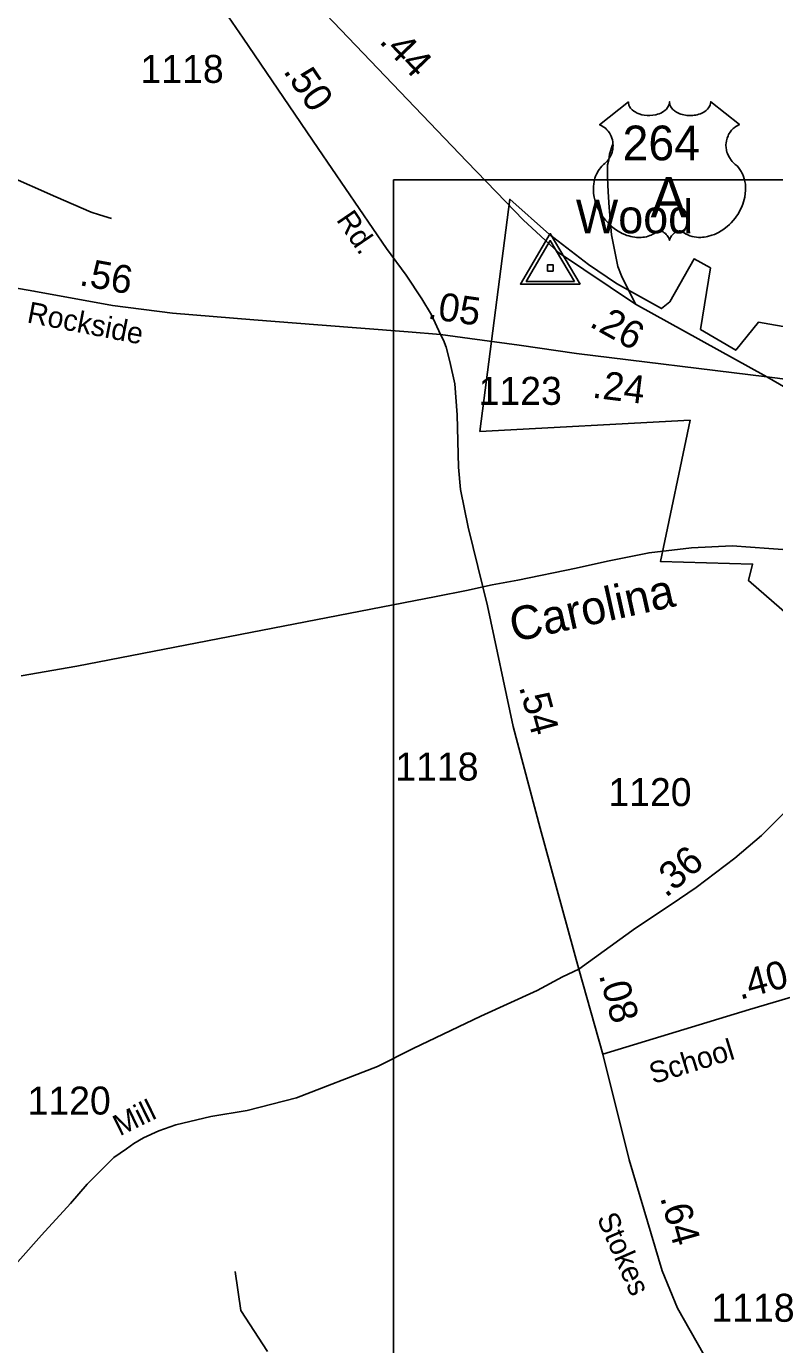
# Model space of a CAD drawing. Extents: x 2220236 to 2384410, y 720751 to 894131.
# Drawn here: x 2229809 to 2233152, y 740224 to 746114 of the extents above; entities that cross this region are included whole.
import ezdxf

# ---------------------------------------------------------------- set-up
doc = ezdxf.new("R2010")
doc.units = 0
doc.layers.add('Default', color=7, linetype='Continuous')

msp = doc.modelspace()

# ---------------------------------------------------------------- linework, layer by layer
at = {"layer": 'Default'}
msp.add_line((2232384.7, 741521.8), (2232276.8, 741902.5), dxfattribs=at)
for points in [[(2231659.5, 744737.4), (2231619.3, 744825.2), (2231575.4, 744896.6), (2231505.9, 745002.7), (2231418.1, 745121.7), (2231112.4, 745569.3), (2230777.7, 746061.6), (2230580.2, 746348.9), (2230512.5, 746456.9), (2230463.1, 746550.2), (2230430.2, 746627.1), (2230406.4, 746714.9), (2230384.5, 746824.7), (2230361.1, 746991.9)], [(2230361.1, 746991.9), (2230447.5, 746900.6), (2230620, 746722.5), (2230949.2, 746376.9), (2231776.5, 745511.2), (2231950.2, 745330.8), (2232027.5, 745250.6), (2232186.5, 745104.3), (2232530.4, 744873.7), (2233116.5, 744547.9)], [(2232427, 745585.6), (2232414.2, 745543.5), (2232410.6, 745517.9), (2232405.1, 745495.9), (2232405.1, 745468.5), (2232405.1, 745439.2), (2232406.9, 745406.2), (2232408.7, 745375.1), (2232412.4, 745305.6), (2232423.4, 745183), (2232450.8, 745042), (2232467.3, 744999.9), (2232530.4, 744873.7)], [(2229152, 745060.9), (2229225.1, 745149.1), (2229349.5, 745299.2), (2229462.9, 745452.9), (2229501.3, 745496.9), (2229521.4, 745511.5), (2229532.4, 745515.2), (2229550.1, 745516.1), (2229570.8, 745513.3), (2229616.5, 745498.7), (2229718.9, 745451.1), (2229940.3, 745352.3), (2230097.5, 745284.6), (2230136, 745271.8), (2230189, 745255.3)], [(2231448.3, 745428), (2239755.4, 745428), (2239755.4, 740165.1), (2231448.3, 740165.1), (2231448.3, 745428)], [(2233447.8, 743279.8), (2233035, 743638), (2233053.2, 743711.6), (2232642, 743722.7), (2232774, 744354.4), (2231834.8, 744304.5), (2231968, 745341.8), (2232145.8, 745184.3), (2232319.5, 745051.1), (2232444.8, 744966.2), (2232646.8, 744853.2), (2232683.2, 744883.9), (2232792.2, 745075.2), (2232865, 745034.9), (2232820.5, 744760.3), (2232978.2, 744667.4), (2233079.2, 744792.6), (2233240.5, 744765.2)], [(2233447.8, 743279.8), (2233035, 743638), (2233053.2, 743711.6), (2232642, 743722.7), (2232774, 744354.4), (2231834.8, 744304.5), (2231968, 745341.8), (2232145.8, 745184.3), (2232319.5, 745051.1), (2232444.8, 744966.2), (2232646.8, 744853.2), (2232683.2, 744883.9), (2232792.2, 745075.2), (2232865, 745034.9), (2232820.5, 744760.3), (2232978.2, 744667.4), (2233079.2, 744792.6), (2233240.5, 744765.2)], [(2228710.3, 745149.1), (2229152, 745060.9), (2229214.1, 745048.5), (2229583.6, 744975.3), (2229842.4, 744931.4), (2230193.6, 744867.3), (2230461.5, 744832.5), (2230825.5, 744803.2), (2231110.8, 744781.3), (2231514.1, 744750.2), (2231659.5, 744737.4)], [(2231848.3, 743610.2), (2231782.9, 743877.2), (2231748.2, 744045.6), (2231739, 744144.4), (2231733.6, 744378.6), (2231722.6, 744517.7), (2231700.6, 744616.6), (2231684.2, 744680.6), (2231672.3, 744711.7), (2231659.5, 744737.4)], [(2231659.5, 744737.4), (2231789.3, 744719.1), (2232010.7, 744689.8), (2232266.7, 744653.2), (2233116.5, 744547.9)], [(2233116.5, 744547.9), (2233680.6, 744476.6), (2233895.5, 744457.6), (2233974.9, 744449), (2234618.8, 744423), (2234693.1, 744419.6), (2234803.6, 744419.6), (2235035.8, 744409.2)], [(2233116.5, 744547.9), (2233770.4, 744170.9), (2234285.3, 743887.2), (2234406, 743825), (2234484.6, 743784.7), (2234587, 743740.8), (2234648.5, 743711.6), (2234722.6, 743682.3), (2234794.9, 743656.8), (2234904.5, 743623.8), (2234995.2, 743597.9), (2235034.9, 743591)], [(2229784.7, 743212.2), (2230034.1, 743256.3), (2231638.9, 743567.2), (2231774.6, 743594.4), (2231890.3, 743619.2), (2232004.1, 743640.2), (2232265.6, 743694.3), (2232405.4, 743725.4), (2232590.9, 743762.9), (2232780.7, 743784.4), (2232962.4, 743793.9), (2233126.5, 743781.3), (2233250.5, 743772.2), (2233448.7, 743743.9), (2233655, 743697.7), (2233873.3, 743643.4), (2236153.5, 743006.3), (2239641.8, 742035), (2241914, 741399.8), (2243637.2, 740920.1)], [(2232276.8, 741902.5), (2232103.9, 742532), (2231983.2, 742985.9), (2231869.2, 743525), (2231848.3, 743610.2)], [(2236084.2, 742760.1), (2235732.6, 742851.1), (2235361.2, 742963.9), (2234889, 743093.5), (2234483.3, 743207.5), (2234115.2, 743323.5), (2234029.2, 743341.8), (2233946.9, 743347.3), (2233886.5, 743338.2), (2233859.2, 743325.9), (2233780.5, 743290.6), (2233700.4, 743211.9), (2233568.5, 743037.2), (2233416.1, 742830), (2233319.2, 742717.2), (2233184.2, 742590.2), (2233093, 742499.5), (2232973.9, 742398.6), (2232801, 742267.2), (2232689.7, 742190.3), (2232530.6, 742085.2), (2232276.8, 741902.5)], [(2232384.7, 741521.8), (2233039.2, 741721.9), (2233422.5, 741834.2), (2233807.5, 741939.6), (2234194.2, 742031.1), (2234389.2, 742071.9), (2234691.3, 742131.3), (2234774.2, 742146.9), (2235456.1, 742290.2)], [(2232276.8, 741902.5), (2232203.6, 741867.7), (2232090.2, 741807.3), (2231839.6, 741692), (2231536.9, 741547.4), (2231377.8, 741466.9), (2231015.7, 741327.8), (2230795.3, 741271.1), (2230632.5, 741243.6), (2230477.1, 741207), (2230400.2, 741179.6), (2230332.6, 741148.5), (2230288.7, 741122.8), (2230255.7, 741099), (2230199.9, 741060.6), (2230080.9, 740941.7), (2230005.8, 740855), (2229876.9, 740714.1), (2228818.2, 739523.3), (2228748.6, 739463.8), (2228736.9, 739450.9)], [(2234109.6, 738638.8), (2233746.3, 738954.1), (2233526.9, 739151.8), (2233398.8, 739294.5), (2233201.3, 739596.5), (2232862, 740132.7), (2232717.6, 740387.1), (2232649, 740553.7), (2232501.7, 741049.6), (2232384.7, 741521.8)], [(2230885.3, 740193.4), (2230767.4, 740376.2), (2230741.4, 740550.6)]]:
    msp.add_lwpolyline(points, dxfattribs=at)
for points in [[(2232498.1, 745777.3), (2232498.4, 745772), (2232499.7, 745765.7), (2232500.7, 745762.4), (2232503.6, 745756.2), (2232508.5, 745748.8), (2232515.3, 745741.6), (2232523, 745735.3), (2232528.1, 745732), (2232536.9, 745727.2), (2232546.8, 745723.1), (2232557.9, 745719.9), (2232569.3, 745717.6), (2232581.6, 745716.2), (2232593.9, 745716), (2232607.1, 745717), (2232621.7, 745719.8), (2232628.4, 745721.5), (2232635.9, 745724.1), (2232642.9, 745727), (2232650.6, 745731.1), (2232656.7, 745735.1), (2232661.6, 745738.6), (2232668.4, 745745.1), (2232673.8, 745751.9), (2232676.1, 745755.7), (2232678.1, 745759.3), (2232680.8, 745767.1), (2232681.5, 745770.5), (2232682.1, 745777.6), (2232682.5, 745771.6), (2232683.1, 745767.9), (2232684.1, 745764.3), (2232685.6, 745760.4), (2232688.4, 745754.9), (2232691.4, 745750.3), (2232697.2, 745743.6), (2232700.7, 745740.2), (2232704, 745737.6), (2232712.7, 745731.6), (2232722.9, 745726.4), (2232727.9, 745724.2), (2232733.1, 745722.4), (2232739.6, 745720.4), (2232746.4, 745718.8), (2232753.1, 745717.7), (2232759.9, 745716.7), (2232766.9, 745716.2), (2232772.6, 745716), (2232779.6, 745716.1), (2232786, 745716.5), (2232792.7, 745717.2), (2232799.9, 745718.4), (2232805.8, 745719.7), (2232813.5, 745721.8), (2232820.5, 745724.3), (2232826.7, 745726.9), (2232834.7, 745731.1), (2232841.1, 745735.1), (2232845.8, 745738.9), (2232851.4, 745744.1), (2232856.8, 745750.3), (2232859.9, 745754.8), (2232862.1, 745759.4), (2232864.1, 745764.3), (2232865.4, 745769.4), (2232866, 745773.9), (2232866.1, 745777.7), (2232994.7, 745675.3), (2232991.7, 745674.1), (2232984.7, 745670.7), (2232979.1, 745667.4), (2232970.3, 745661.2), (2232966.5, 745657.8), (2232962.7, 745654.2), (2232959.2, 745650.4), (2232956.1, 745646.8), (2232952.4, 745641.7), (2232949.1, 745636.5), (2232945.8, 745630.8), (2232943.4, 745625.9), (2232939.5, 745615.5), (2232937.6, 745609), (2232936.3, 745603.5), (2232934.8, 745592), (2232934.4, 745586.5), (2232934.4, 745581.1), (2232934.8, 745575.4), (2232935.3, 745570), (2232936.3, 745564.3), (2232937.2, 745559.2), (2232938.8, 745553.1), (2232941.1, 745545.9), (2232943.9, 745539), (2232949.7, 745527.9), (2232957.3, 745516.5), (2232962.7, 745510.1), (2232968, 745504.6), (2232976, 745497.9), (2232980.2, 745494.1), (2232985.2, 745489.2), (2232993.2, 745479.8), (2232996.5, 745475.4), (2232999.8, 745470.5), (2233002.8, 745465.4), (2233005.9, 745459.9), (2233008.3, 745455.1), (2233012.8, 745444.1), (2233016.1, 745433.4), (2233017.6, 745427.8), (2233020, 745415.2), (2233021, 745408.9), (2233021.9, 745396.6), (2233022, 745381.7), (2233020.8, 745367.6), (2233018.2, 745351.1), (2233016, 745341.2), (2233012.6, 745329.8), (2233009.3, 745319.8), (2233003.4, 745305.1), (2232998.2, 745294.5), (2232991.5, 745282), (2232986.9, 745274.5), (2232981.5, 745266.5), (2232974.7, 745257.2), (2232966.8, 745247.3), (2232957.3, 745236.9), (2232949.6, 745229.2), (2232939.6, 745220.3), (2232933.5, 745215.2), (2232924.9, 745208.7), (2232913, 745200.8), (2232901.3, 745194), (2232891.4, 745189), (2232882.6, 745185.2), (2232871.2, 745180.8), (2232852.2, 745175.6), (2232845.3, 745174.1), (2232837.1, 745172.9), (2232829.4, 745172.2), (2232822, 745171.7), (2232812, 745171.7), (2232802, 745172.5), (2232792.6, 745173.8), (2232782.8, 745175.9), (2232772.5, 745178.9), (2232763.2, 745182.6), (2232753.8, 745187.2), (2232737.9, 745197.2), (2232733.3, 745199.7), (2232730.7, 745200.4), (2232724.6, 745200.7), (2232718.8, 745199.4), (2232712.9, 745197.1), (2232709.3, 745195.2), (2232704.6, 745192.1), (2232700.9, 745189.2), (2232696.5, 745185), (2232693.5, 745181.5), (2232691.2, 745178.8), (2232686.7, 745171.7), (2232685.1, 745168.4), (2232683.4, 745164), (2232681.9, 745157.7), (2232679.9, 745165.7), (2232677.6, 745171), (2232674.8, 745175.6), (2232672, 745179.6), (2232667.5, 745184.8), (2232663.5, 745188.6), (2232658.6, 745192.6), (2232653.4, 745195.7), (2232649.3, 745197.8), (2232645.5, 745199.3), (2232640.9, 745200.4), (2232637.1, 745200.7), (2232634, 745200.7), (2232629.7, 745199.7), (2232623.9, 745195.5), (2232618.4, 745191.7), (2232612.4, 745188), (2232605.2, 745184.2), (2232600, 745181.7), (2232593.7, 745179.3), (2232586.5, 745176.9), (2232578.6, 745174.8), (2232570.4, 745173.2), (2232563.3, 745172.1), (2232555.6, 745171.4), (2232548.7, 745171.2), (2232541.5, 745171.2), (2232534.7, 745171.8), (2232526.9, 745172.5), (2232517.2, 745173.9), (2232509.1, 745175.7), (2232500.6, 745178), (2232491.9, 745180.7), (2232482.6, 745184.3), (2232470.9, 745189.4), (2232462.7, 745193.6), (2232449.9, 745201), (2232434.9, 745211.4), (2232423.5, 745220.6), (2232415.2, 745228.1), (2232403, 745240.5), (2232395.8, 745248.7), (2232384.5, 745263.3), (2232377.3, 745273.8), (2232372.6, 745281.6), (2232365.8, 745294), (2232362, 745301.9), (2232357.2, 745313.3), (2232353.3, 745323.7), (2232350.2, 745333.6), (2232348.4, 745339.9), (2232346, 745350.9), (2232344.5, 745358.7), (2232343.1, 745369.4), (2232342.3, 745380.7), (2232342.1, 745391.2), (2232342.4, 745399.8), (2232343.4, 745409.9), (2232345.1, 745420.6), (2232347.2, 745429.8), (2232349, 745436.4), (2232351.7, 745444.5), (2232355.4, 745453.4), (2232359.6, 745461.9), (2232363.7, 745469), (2232368.8, 745476.6), (2232373.8, 745483), (2232380.3, 745490.2), (2232387.2, 745496.7), (2232393.4, 745501.8), (2232400.9, 745509.1), (2232404.8, 745513.5), (2232409.4, 745519.6), (2232413.2, 745525.3), (2232416.1, 745530.4), (2232420, 745538), (2232422.4, 745543.6), (2232425.3, 745552.2), (2232426.8, 745558.3), (2232428.3, 745566.1), (2232429.3, 745573.5), (2232429.7, 745582.7), (2232429.5, 745590.3), (2232428.5, 745599.2), (2232426.8, 745607.7), (2232424.8, 745615.2), (2232421.6, 745623.7), (2232418.7, 745629.9), (2232413.8, 745638.3), (2232408.3, 745646.2), (2232402.6, 745652.5), (2232396.9, 745658.2), (2232391.5, 745662.5), (2232386.3, 745666.2), (2232379.7, 745670.2), (2232373.4, 745673.3), (2232369.5, 745674.9)], [(2232283.4, 744962.7), (2232149.4, 745188.8), (2232015.9, 744962.7)], [(2232257.4, 744974.9), (2232041.9, 744974.9), (2232149.4, 745157)], [(2232161.7, 745021.4), (2232161.7, 745049.7), (2232137.5, 745049.7), (2232137.5, 745021.4)]]:
    msp.add_lwpolyline(points, close=True, dxfattribs=at)

# ---------------------------------------------------------------- texts
for s, height, rotation, p in [('.44', 125, 313.75506, (2231380.9, 746044.2)), ('.50', 125, 304.21033, (2230953.4, 745914.3)), ('Rd.', 95, 304.25355, (2231190.8, 745250.4)), ('.56', 125, 349.66257, (2230041.2, 744958.6)), ('.05', 125, 351.97754, (2231597.9, 744809.2)), ('Rockside', 95, 349.02825, (2229807.5, 744792.2)), ('.26', 125, 330.93749, (2232319.3, 744776.4)), ('.24', 125, 352.93878, (2232333.5, 744456)), ('Carolina', 150, 12.5476, (2231986.3, 743362.7)), ('.54', 125, 285.19363, (2232008.9, 743163.4)), ('.36', 125, 40.29089, (2232666, 742218.2)), ('.40', 125, 15.00144, (2232997, 741764.8)), ('.08', 125, 285.39883, (2232365.8, 741875.4)), ('School', 95, 17.11619, (2232608.5, 741387.8)), ('Mill', 95, 26.18373, (2230225.7, 741154.3)), ('.64', 125, 285.72595, (2232639.2, 740881.7)), ('Stokes', 95, 293.6823, (2232356, 740789.8))]:
    msp.add_text(s, height=height, rotation=rotation, dxfattribs=at).set_placement(p)
for s, height, p in [('1118', 125, (2230318.5, 745861.9)), ('264', 155, (2232472.4, 745516)), ('A', 180, (2232597.6, 745261.1)), ('Wood', 150, (2232263.7, 745189.9)), ('1123', 125, (2231829.1, 744423.4)), ('1118', 125, (2231457, 742744.7)), ('1120', 125, (2232408.8, 742630.6)), ('1120', 125, (2229813.8, 741252.4)), ('1118', 125, (2232869.1, 740326.5))]:
    msp.add_text(s, height=height, dxfattribs=at).set_placement(p)

doc.saveas('drawing.dxf')
